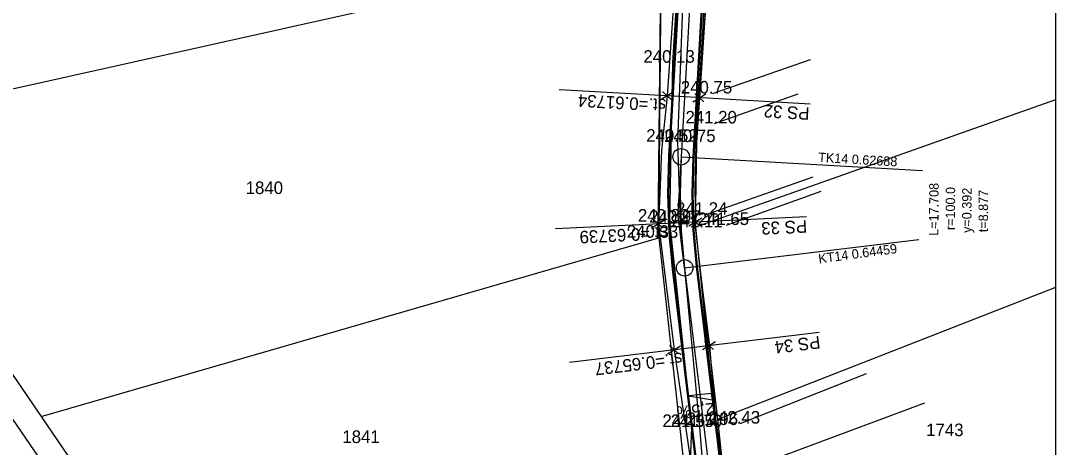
# Model space of a CAD drawing. Extents: x -601754 to -601440, y -1201912 to -1200862.
# Drawn here: x -601619.2 to -601454.6, y -1201490.6 to -1201422.6 of the extents above; entities that cross this region are included whole.
import ezdxf

# ---------------------------------------------------------------- set-up
doc = ezdxf.new("R2010")
doc.units = 0
for name, color, linetype in [('Hranice parcel', 7, 'Continuous'), ('Parcelní čísla', 7, 'Continuous'), ('u_drén', 7, 'Continuous'), ('u_hrany', 7, 'Continuous'), ('u_krizky', 7, 'Continuous'), ('u_návrh', 7, 'Continuous'), ('u_oblouky', 7, 'Continuous'), ('u_osa', 7, 'Continuous'), ('u_popis oblouky', 7, 'Continuous'), ('u_pricne_cesta', 7, 'Continuous'), ('u_sklony', 7, 'Continuous'), ('u_terénní úpravy', 7, 'Continuous'), ('u_vyska', 7, 'Continuous'), ('x_rám', 7, 'Continuous')]:
    doc.layers.add(name, color=color, linetype=linetype)

msp = doc.modelspace()

# ---------------------------------------------------------------- linework, layer by layer
at = {"layer": 'Hranice parcel'}
for p, q in [((-601647.48, -1201439.51), (-601517.31, -1201410.46)), ((-601647.48, -1201439.51), (-601615.9, -1201485.66)), ((-601508.25, -1201486.13), (-601511.82, -1201455.51)), ((-601615.9, -1201485.66), (-601517.67, -1201457.2)), ((-601517.67, -1201457.2), (-601513.82, -1201491.91)), ((-601615.9, -1201485.66), (-601595.45, -1201515.56))]:
    msp.add_line(p, q, dxfattribs=at)
for points in [[(-601751.58, -1201306.17), (-601748.76, -1201310.71), (-601730.19, -1201336.75), (-601687.14, -1201388.63), (-601598.97, -1201517.51), (-601569.38, -1201585.08), (-601570.68, -1201592.44)], [(-601511.82, -1201455.51), (-601511.63, -1201442.04), (-601509.82, -1201414.6), (-601509.57, -1201401.34), (-601512.41, -1201389.28), (-601514.66, -1201382.62)], [(-601517.31, -1201410.46), (-601517.81, -1201455.91), (-601517.67, -1201457.2)], [(-601454.58, -1201435.22), (-601511.82, -1201455.51)], [(-601454.58, -1201465.12), (-601508.25, -1201486.13)], [(-601505.47, -1201514.18), (-601505.62, -1201511.23), (-601508.14, -1201487.04), (-601508.25, -1201486.13)]]:
    msp.add_lwpolyline(points, dxfattribs=at)
at = {"layer": 'u_drén'}
msp.add_lwpolyline([(-601553.19, -1201317.86), (-601552.87, -1201318.69), (-601546.07, -1201333.75), (-601538.46, -1201348.42), (-601530.07, -1201362.64), (-601525.78, -1201369.47), (-601523.23, -1201373.89), (-601521.02, -1201378.46), (-601519.17, -1201383.18), (-601517.66, -1201388.07), (-601516.53, -1201392.26), (-601515.32, -1201397.6), (-601514.55, -1201402.98), (-601514.21, -1201408.4), (-601514.3, -1201413.88), (-601516.03, -1201444.23), (-601516.2, -1201450.21), (-601516.01, -1201456.23), (-601515.46, -1201462.19), (-601510.25, -1201505.37), (-601509.83, -1201509.66), (-601509.59, -1201513.94), (-601509.54, -1201518.24), (-601509.79, -1201540.62)], dxfattribs=at)
at = {"layer": 'u_hrany'}
for points in [[(-601510.66, -1201493.25), (-601511.13, -1201487.34), (-601514.2, -1201454.81), (-601514.64, -1201441.92), (-601513.13, -1201401.75), (-601514.86, -1201390.2), (-601518.87, -1201379.54), (-601520.9, -1201374.92)], [(-601515.97, -1201390.87), (-601514.58, -1201414.64), (-601515.47, -1201429.34), (-601515.96, -1201454.63), (-601512.47, -1201487.32), (-601513.15, -1201505.52)], [(-601512.26, -1201390.52), (-601510.47, -1201401.41), (-601510.09, -1201413.72), (-601511.79, -1201441.97), (-601511.82, -1201455.52), (-601508.66, -1201487.01), (-601505.94, -1201512.07), (-601505.14, -1201523.95), (-601505.37, -1201547.09), (-601506.1, -1201561.67), (-601507, -1201580.71), (-601507.44, -1201612.51), (-601506.59, -1201624.18), (-601504.84, -1201632.93)], [(-601517.26, -1201410.36), (-601517.73, -1201457.2)], [(-601509.14, -1201434.24), (-601493.54, -1201428.85)], [(-601508.78, -1201439.01), (-601495.5, -1201434.28)], [(-601510.28, -1201453.55), (-601493.09, -1201447.49)], [(-601506.87, -1201455.17), (-601491.82, -1201449.78)], [(-601504.71, -1201486.78), (-601484.63, -1201478.81)], [(-601504.1, -1201494.18), (-601475.33, -1201483.46)]]:
    msp.add_lwpolyline(points, dxfattribs=at)
at = {"layer": 'u_krizky'}
for p, q in [((-601515.36, -1201434.03), (-601517.42, -1201435.31)), ((-601515.66, -1201435.25), (-601517.08, -1201433.94)), ((-601510.19, -1201434.32), (-601512.25, -1201435.6)), ((-601510.49, -1201435.55), (-601511.91, -1201434.23)), ((-601516.76, -1201454.38), (-601518.82, -1201455.66)), ((-601517.06, -1201455.61), (-601518.48, -1201454.29)), ((-601510.84, -1201454.1), (-601512.89, -1201455.38)), ((-601511.13, -1201455.32), (-601512.56, -1201454.01)), ((-601514.23, -1201474.46), (-601516.28, -1201475.74)), ((-601514.52, -1201475.68), (-601515.95, -1201474.37)), ((-601508.65, -1201473.79), (-601510.7, -1201475.06)), ((-601508.95, -1201475.01), (-601510.37, -1201473.69))]:
    msp.add_line(p, q, dxfattribs=at)
at = {"layer": 'u_návrh'}
for points in [[(-601549.75, -1201316.3), (-601549.39, -1201317.23), (-601542.68, -1201332.11), (-601535.16, -1201346.59), (-601526.84, -1201360.67), (-601522.55, -1201367.52), (-601519.89, -1201372.13), (-601517.56, -1201376.95), (-601515.6, -1201381.93), (-601514.03, -1201387.02), (-601512.87, -1201391.36), (-601511.61, -1201396.91), (-601510.79, -1201402.59), (-601510.43, -1201408.32), (-601510.53, -1201414.01), (-601512.26, -1201444.39), (-601512.42, -1201450.21), (-601512.24, -1201456), (-601511.71, -1201461.79), (-601506.5, -1201504.96), (-601506.06, -1201509.37), (-601505.82, -1201513.81), (-601505.77, -1201518.24), (-601506.19, -1201556.5)], [(-601553.14, -1201317.8), (-601552.81, -1201318.66), (-601546.01, -1201333.72), (-601538.39, -1201348.39), (-601530, -1201362.6), (-601525.72, -1201369.43), (-601523.16, -1201373.86), (-601520.96, -1201378.43), (-601519.1, -1201383.16), (-601517.59, -1201388.04), (-601516.46, -1201392.25), (-601515.25, -1201397.59), (-601514.48, -1201402.97), (-601514.13, -1201408.4), (-601514.23, -1201413.88), (-601515.96, -1201444.23), (-601516.12, -1201450.21), (-601515.93, -1201456.22), (-601515.39, -1201462.18), (-601510.17, -1201505.36), (-601509.75, -1201509.65), (-601509.52, -1201513.93), (-601509.47, -1201518.24), (-601509.71, -1201540.62)], [(-601514.38, -1201413.87), (-601516.11, -1201444.23), (-601516.27, -1201450.21), (-601516.08, -1201456.23), (-601515.54, -1201462.2), (-601510.32, -1201505.38), (-601509.9, -1201509.66), (-601509.67, -1201513.94), (-601509.62, -1201518.24), (-601509.86, -1201540.61)], [(-601510.38, -1201414.02), (-601512.11, -1201444.4), (-601512.27, -1201450.21), (-601512.09, -1201455.99), (-601511.56, -1201461.78), (-601506.35, -1201504.94), (-601505.91, -1201509.36), (-601505.67, -1201513.81), (-601505.62, -1201518.24), (-601506.04, -1201556.51)]]:
    msp.add_lwpolyline(points, dxfattribs=at)
at = {"layer": 'u_oblouky'}
for p, q in [((-601514.11, -1201444.31), (-601514.61, -1201453.17)), ((-601514.11, -1201444.31), (-601475.69, -1201446.5)), ((-601513.55, -1201461.99), (-601514.61, -1201453.17)), ((-601513.55, -1201461.99), (-601476.29, -1201457.49))]:
    msp.add_line(p, q, dxfattribs=at)
for centre in [(-601514.11, -1201444.31), (-601513.55, -1201461.99)]:
    msp.add_circle(centre, 1.31, dxfattribs=at)
at = {"layer": 'u_osa'}
msp.add_lwpolyline([(-601512.38, -1201413.95), (-601514.11, -1201444.31), (-601514.27, -1201450.21), (-601514.08, -1201456.11), (-601513.55, -1201461.99), (-601508.33, -1201505.16), (-601507.91, -1201509.51), (-601507.67, -1201513.87), (-601507.62, -1201518.24), (-601508.04, -1201556.38), (-601508.4, -1201559.4), (-601509.41, -1201562.27), (-601511.01, -1201564.85), (-601513.14, -1201567.02), (-601515.68, -1201568.69), (-601576.3, -1201599.45)], dxfattribs=at)
at = {"layer": 'u_pricne_cesta'}
for points in [[(-601493.6, -1201435.93), (-601513.57, -1201434.79), (-601533.53, -1201433.65)], [(-601494.15, -1201453.85), (-601514.12, -1201454.81), (-601534.1, -1201455.78)], [(-601492.16, -1201472.28), (-601512.02, -1201474.68), (-601531.87, -1201477.08)]]:
    msp.add_lwpolyline(points, dxfattribs=at)
at = {"layer": 'u_sklony'}
for p, q in [((-601516.18, -1201453.03), (-601516.13, -1201454.58)), ((-601515.99, -1201457.2), (-601515.85, -1201458.76))]:
    msp.add_line(p, q, dxfattribs=at)
msp.add_lwpolyline([(-601509.27, -1201481.99), (-601512.95, -1201482.37), (-601509.14, -1201483.02)], close=True, dxfattribs=at)
at = {"layer": 'u_terénní úpravy'}
for points in [[(-601514.93, -1201414.63), (-601516.33, -1201434.63), (-601517.23, -1201443.32), (-601517.51, -1201450.18), (-601517.73, -1201454.99), (-601515.19, -1201475.06), (-601512.31, -1201494.84), (-601511.29, -1201505.25), (-601511, -1201509.5), (-601510.74, -1201514.55), (-601511.19, -1201526.6), (-601511.29, -1201528.95), (-601511.23, -1201535.02), (-601513.15, -1201556), (-601514.13, -1201558.52), (-601515.24, -1201561.13), (-601516.66, -1201563.29), (-601517.73, -1201564.66), (-601519.33, -1201566.6), (-601521.68, -1201567.78), (-601538.8, -1201577.41), (-601577.28, -1201597.59)], [(-601509.86, -1201414.92), (-601511.16, -1201434.93), (-601511.79, -1201442.27), (-601511.95, -1201449.35), (-601511.81, -1201454.7), (-601511.82, -1201455.51), (-601511.2, -1201461.7), (-601509.62, -1201474.39), (-601508.62, -1201486.14), (-601507.39, -1201494.24), (-601506.28, -1201504.86), (-601505.75, -1201510), (-601505.46, -1201514.4), (-601505.14, -1201523.95), (-601505.17, -1201535.09), (-601505.65, -1201556.08), (-601506.35, -1201585.45)]]:
    msp.add_lwpolyline(points, dxfattribs=at)
at = {"layer": 'x_rám'}
msp.add_lwpolyline([(-601454.58, -1200862.35), (-601454.58, -1201912.35), (-601751.58, -1201912.35), (-601751.58, -1200862.35)], close=True, dxfattribs=at)

# ---------------------------------------------------------------- texts
at = {"layer": 'Parcelní čísla'}
for s, p in [('1840', (-601583.38, -1201450.24)), ('1841', (-601568, -1201489.87)), ('1743', (-601475.13, -1201488.78))]:
    msp.add_text(s, height=2, dxfattribs=at).set_placement(p)
at = {"layer": 'u_oblouky'}
for s, p in [('L=17.708', (-601473.18, -1201456.89)), ('r=100.0', (-601470.55, -1201455.98)), ('y=0.392', (-601467.93, -1201456.43)), ('t=8.877', (-601465.3, -1201456.32))]:
    msp.add_text(s, height=1.5, rotation=89.704, dxfattribs=at).set_placement(p)
at = {"layer": 'u_popis oblouky'}
for s, rotation, p in [('TK14 0.62688', 356.7401, (-601492.34, -1201445.13)), ('KT14 0.64459', 7.5366, (-601492.17, -1201461.29))]:
    msp.add_text(s, height=1.5, rotation=rotation, dxfattribs=at).set_placement(p)
at = {"layer": 'u_pricne_cesta'}
for s, rotation, p in [('st.=0.61734', 176.7401, (-601516.44, -1201435.15)), ('PS 32', 176.7401, (-601493.63, -1201436.45)), ('PS 33', 182.7609, (-601494.12, -1201454.38)), ('st.=0.63739', 182.7609, (-601516.27, -1201455.44)), ('PS 34', 186.8862, (-601492.1, -1201472.8)), ('st.=0.65737', 186.8862, (-601514, -1201475.45))]:
    msp.add_text(s, height=2, rotation=rotation, dxfattribs=at).set_placement(p)
at = {"layer": 'u_sklony'}
msp.add_text('2,5%', height=2, rotation=186.0072, dxfattribs=at).set_placement((-601508.87, -1201483.44))
at = {"layer": 'u_vyska'}
for s, p in [('240.13', (-601520.11, -1201429.34)), ('240.75', (-601514.16, -1201434.24)), ('241.20', (-601513.42, -1201439.01)), ('240.52', (-601519.66, -1201441.92)), ('240.75', (-601516.81, -1201441.97)), ('241.24', (-601514.92, -1201453.55)), ('240.82', (-601520.98, -1201454.63)), ('240.97', (-601519.19, -1201454.81)), ('241.11', (-601515.69, -1201455.52)), ('241.65', (-601511.48, -1201455.17)), ('240.33', (-601522.75, -1201457.2)), ('242.43', (-601509.72, -1201486.78)), ('241.55', (-601517.08, -1201487.32)), ('241.70', (-601515.78, -1201487.34)), ('241.96', (-601513.24, -1201487.01))]:
    msp.add_text(s, height=2, dxfattribs=at).set_placement(p)

doc.saveas('drawing.dxf')
